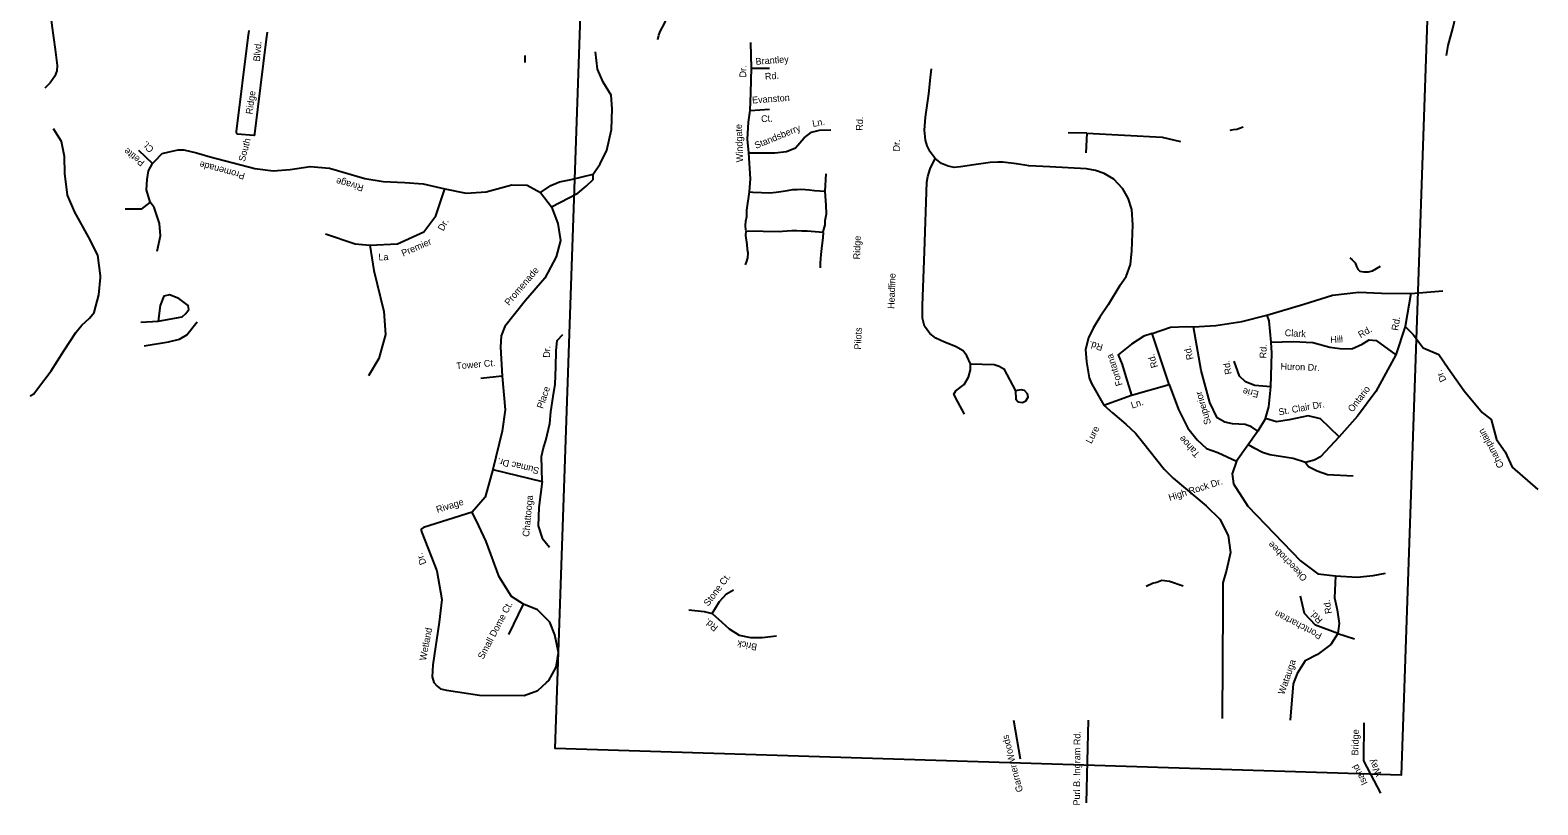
# Model space of a CAD drawing. Extents: x 2308163 to 2335412, y -96774 to 127732.
# Drawn here: x 2319297 to 2321125, y 13074 to 14013 of the extents above; entities that cross this region are included whole.
import ezdxf

# ---------------------------------------------------------------- set-up
doc = ezdxf.new("R2010")
doc.units = 0
for name, color, linetype in [('Old_Level_10', 7, 'Continuous'), ('Old_Level_35', 7, 'Continuous'), ('Old_Level_63', 7, 'Continuous')]:
    doc.layers.add(name, color=color, linetype=linetype)

msp = doc.modelspace()

# ---------------------------------------------------------------- linework, layer by layer
at = {"layer": 'Old_Level_35'}
for p, q in [((2319561.2, 14004.4), (2319562.3, 14012.8)), ((2319584, 14010.7), (2319582.9, 14002.3)), ((2319897.2, 13974.2), (2319896.9, 13982.6)), ((2320260.6, 13818.3), (2320262.1, 13839.2))]:
    msp.add_line(p, q, dxfattribs=at)
for points in [[(2320058, 14002.1), (2320058.9, 14007.1), (2320060.6, 14011.6), (2320065.8, 14021.3), (2320072.4, 14036.5), (2320082, 14060.8), (2320090.8, 14085.8), (2320104.8, 14119.7)], [(2319319.2, 14050.1), (2319319.7, 14046), (2319323, 14019.1), (2319327.2, 13989.8), (2319329.6, 13970.4), (2319329.3, 13963.9), (2319326.9, 13957.6), (2319320.9, 13949.3), (2319314.7, 13943)], [(2321014.3, 13982.6), (2321016.1, 13994.8), (2321022, 14015.4), (2321025.4, 14030.8), (2321026.1, 14038.3)], [(2319582.9, 14002.3), (2319569, 13887.5), (2319568.9, 13886.5), (2319568.8, 13886.1), (2319568.6, 13885.8), (2319568.3, 13885.7), (2319567.9, 13885.6), (2319548.4, 13887.3), (2319547.7, 13887.7), (2319547.3, 13888.3), (2319547, 13889), (2319546.9, 13889.6), (2319546.8, 13890.5), (2319561.2, 14004.4)], [(2319929.1, 13799.2), (2319960.9, 13815.9), (2319970.9, 13824.4), (2319979.3, 13832.2), (2319979.5, 13838.6), (2319988, 13851.2), (2319995.9, 13867.9), (2320001.6, 13892.8), (2320002.4, 13917.8), (2320001.4, 13934.7), (2319991.4, 13950.4), (2319984.7, 13966), (2319982.4, 13987)], [(2320169.1, 13817.2), (2320170.3, 13833.2), (2320168.1, 13864.7), (2320166.7, 13881.3), (2320167.8, 13901.9), (2320169.9, 13915.9), (2320170.6, 13937.3), (2320171.3, 13967.2), (2320170.6, 13998.4)], [(2320171.3, 13967.2), (2320193.1, 13967.2)], [(2320394, 13857.7), (2320388, 13865.9), (2320384.6, 13873.1), (2320382.4, 13880), (2320381.1, 13891.9), (2320382.5, 13907.9), (2320386.5, 13936), (2320388.5, 13956), (2320389.1, 13962.7), (2320389.5, 13966.3)], [(2320169.9, 13915.9), (2320193.4, 13917.5)], [(2319382.1, 13715.5), (2319378.7, 13740.4), (2319367.6, 13762.7), (2319350.8, 13792.9), (2319342, 13813.4), (2319338.8, 13839.5), (2319338.3, 13860.3), (2319334.8, 13878.2), (2319325.3, 13893.9)], [(2320751.9, 13892), (2320756, 13892.8), (2320759.9, 13893.4), (2320763.3, 13894.5), (2320767.6, 13896.2)], [(2320168.1, 13864.7), (2320199.8, 13864.5), (2320213.7, 13866.3), (2320224.9, 13870.6), (2320235.4, 13882.8), (2320244, 13889.7), (2320254, 13892.1), (2320267.6, 13892.4)], [(2320578, 13888.3), (2320555.4, 13888.8)], [(2320578, 13888.3), (2320577, 13864.6)], [(2320578, 13888.3), (2320669.5, 13883.5), (2320691.7, 13878.2)], [(2319445.3, 13851.6), (2319428.7, 13867.6)], [(2319442.5, 13804.9), (2319437.7, 13819.9), (2319438.7, 13832.3), (2319440.3, 13842.9), (2319445.3, 13851.6), (2319447.8, 13854.5), (2319457, 13863.7), (2319465.4, 13865.7), (2319476.1, 13868.3), (2319483.3, 13868.1), (2319498.5, 13864.6), (2319515, 13859.9)], [(2319515, 13859.9), (2319569.3, 13845.6), (2319591.4, 13842.9), (2319612.1, 13844.6), (2319636.4, 13848.2), (2319659.9, 13845.9), (2319702.4, 13833.6), (2319724.8, 13829.9), (2319751.3, 13828.5), (2319773.5, 13827.2), (2319799.8, 13820.9), (2319825.3, 13815.6), (2319849.9, 13817.2), (2319880.8, 13826), (2319899.5, 13825.3), (2319915.4, 13816.4), (2319929.1, 13799.2), (2319936.8, 13778.8), (2319940, 13758.5), (2319934.4, 13738.5), (2319920.7, 13712.9), (2319897.6, 13685.6), (2319872.4, 13654), (2319868.1, 13642.9), (2319867.1, 13629.1), (2319869.3, 13594.1), (2319872.8, 13553.1), (2319869, 13527.2), (2319858, 13480.8), (2319848.5, 13447.2), (2319832.6, 13429), (2319773.9, 13410.4), (2319770.8, 13408.5), (2319770.8, 13407), (2319771.7, 13404.5), (2319789.8, 13358.1), (2319796, 13323.5), (2319792.6, 13296), (2319784.9, 13244.1), (2319784.4, 13229.4), (2319786.1, 13222.9), (2319790.4, 13218.3), (2319794.2, 13215.2), (2319801.5, 13213.5), (2319841.7, 13207.2), (2319895.9, 13206.8), (2319912.3, 13213.1), (2319923, 13222.6), (2319925.6, 13225), (2319934.5, 13241.4), (2319937.6, 13259), (2319932.9, 13280.4), (2319927, 13295.8), (2319911.8, 13310.6), (2319894.8, 13317.6), (2319880.3, 13327), (2319865.4, 13350.6), (2319849.6, 13393.5), (2319840.9, 13412.5), (2319832.6, 13429)], [(2320436.8, 13609.1), (2320432.6, 13618.8), (2320428.2, 13624.6), (2320418.6, 13630), (2320405.3, 13635), (2320394.8, 13640), (2320387.6, 13645.7), (2320381.4, 13654.4), (2320378.7, 13664.1), (2320378.7, 13679.5), (2320381.2, 13745.1), (2320384.1, 13828.9), (2320385.2, 13835.8), (2320387.9, 13845.3), (2320394, 13857.7)], [(2320618.1, 13703.7), (2320625.7, 13714.7), (2320630.9, 13729.3), (2320632.4, 13745.8), (2320633.8, 13777.2), (2320632.6, 13796), (2320628.3, 13809.7), (2320621.8, 13820.9), (2320610.6, 13832.9), (2320599.2, 13839.5), (2320588.4, 13843.4), (2320577.5, 13845.3), (2320533.3, 13847.8), (2320507.9, 13849), (2320492.9, 13851.1), (2320476.3, 13853.5), (2320470.3, 13853.4), (2320460.8, 13852.8), (2320440.9, 13850.2), (2320424.8, 13847.5), (2320417, 13846.8), (2320409.9, 13848.4), (2320401.9, 13851.6), (2320394, 13857.7)], [(2319654.9, 13766.3), (2319691, 13754.2), (2319708.6, 13752.6), (2319742.2, 13754.4), (2319774.2, 13769), (2319788.7, 13788.2), (2319799.8, 13820.9)], [(2319915.4, 13816.4), (2319928.1, 13825.1), (2319938.8, 13829.5), (2319952.6, 13832.3), (2319979.5, 13838.6)], [(2320169.1, 13817.2), (2320173.2, 13817), (2320183.5, 13816.5), (2320193.7, 13816.1), (2320201.2, 13816.8), (2320206.8, 13817.6), (2320215.1, 13819.1), (2320221.6, 13820.1), (2320226.8, 13820.1), (2320230.9, 13820.5), (2320237, 13820.1), (2320241.7, 13819.8), (2320247.8, 13819), (2320260.6, 13818.3)], [(2319450.6, 13745.4), (2319454.8, 13764.2), (2319453.5, 13779.1), (2319447, 13798.2), (2319442.5, 13804.9), (2319431.6, 13796.4), (2319412, 13796.5)], [(2320164.7, 13770.8), (2320164.3, 13776.4), (2320164.5, 13781.9), (2320165.7, 13787.5), (2320165.6, 13795.2), (2320169.1, 13817.2)], [(2320258.5, 13768.8), (2320260.6, 13777.4), (2320260.7, 13782.5), (2320262.2, 13790.7), (2320261.8, 13800.8), (2320260.6, 13818.3)], [(2320164, 13728.9), (2320165.8, 13733.4), (2320166.9, 13737.3), (2320167.5, 13743.2), (2320166.5, 13747.5), (2320166.1, 13753.7), (2320164.7, 13764.3), (2320165.1, 13770)], [(2320165.5, 13770.2), (2320205.9, 13769.4), (2320208.9, 13769.7), (2320220.5, 13770.5), (2320226.4, 13770.5), (2320232.5, 13770.1), (2320238.8, 13770.1), (2320258.5, 13768.6)], [(2320255, 13725.2), (2320255.2, 13730.9), (2320255.4, 13736.6), (2320255.8, 13741.3), (2320256.8, 13748.6), (2320258.5, 13762.1), (2320258.9, 13768.2)], [(2319708.6, 13752.6), (2319713.5, 13721.9), (2319725.6, 13672.3), (2319727.6, 13644.6), (2319719.7, 13615.4), (2319707.1, 13594.2)], [(2320897, 13737.2), (2320899.6, 13735), (2320903.3, 13731.5), (2320905.1, 13726.9), (2320906.5, 13723.5), (2320909, 13721.2), (2320913.7, 13720.3), (2320919.4, 13720.3), (2320924.5, 13721.8), (2320934, 13727.1)], [(2319296.8, 13570.2), (2319301.3, 13572.6), (2319305.8, 13578.7), (2319322.1, 13600.5), (2319337.5, 13624.8), (2319352.2, 13646.9), (2319359.4, 13655.7), (2319368.8, 13664.4), (2319374.3, 13671.2), (2319380.2, 13692.5), (2319382.1, 13713.5), (2319382.1, 13715.5)], [(2319430.9, 13659.4), (2319452, 13660.6), (2319481.1, 13666), (2319485.5, 13669.8), (2319489.2, 13674.7), (2319488.5, 13679.8), (2319477, 13687.9), (2319465.8, 13692.7), (2319459, 13690.8), (2319454.5, 13679.7)], [(2320618.1, 13703.7), (2320603.8, 13680.6), (2320593.9, 13665.6), (2320585.9, 13652.1), (2320580, 13640.3), (2320576.5, 13626.4), (2320577.5, 13611.3), (2320580.9, 13592.1), (2320583.7, 13584.9), (2320598.7, 13558.7), (2320609.1, 13549.4), (2320625.2, 13535.8), (2320636.9, 13524.8), (2320645.5, 13514.5), (2320671.6, 13481.4), (2320682.6, 13470.3), (2320722.8, 13436.9), (2320739.2, 13420.7), (2320749.2, 13400.9), (2320752.3, 13380.1), (2320747.2, 13358.9), (2320742.8, 13343.4), (2320743.1, 13315.1), (2320742.1, 13179.2)], [(2320657.1, 13645.7), (2320679.4, 13653.2), (2320699.4, 13654.3), (2320707.3, 13653.7), (2320734.6, 13655.4), (2320766, 13660.4), (2320796.1, 13667.8), (2320841.3, 13681.1), (2320876, 13692.3), (2320907.9, 13695.7), (2320935.2, 13694.7), (2320970.9, 13694.3)], [(2320970.9, 13694.3), (2320964.1, 13654.3), (2320952.7, 13619.7), (2320928.4, 13575.2), (2320906.4, 13545.6), (2320883.8, 13520.4), (2320861.3, 13496), (2320853.8, 13492), (2320843.1, 13489.3), (2320828.2, 13494.1), (2320800, 13498.5), (2320791, 13501.3), (2320781.9, 13506.2), (2320773.9, 13510.8)], [(2320970.9, 13694.3), (2321009.6, 13697.2)], [(2319454.5, 13679.7), (2319452, 13660.6)], [(2319435, 13630.7), (2319464.7, 13635.7), (2319478, 13638.8), (2319486.8, 13644.1), (2319499.4, 13659.8)], [(2320801.6, 13635), (2320799, 13660.9), (2320796.8, 13668)], [(2319917.8, 13466.3), (2319916.9, 13496.6), (2319919.2, 13507.3), (2319922.2, 13515.9), (2319927, 13536.6), (2319928.1, 13550.7), (2319930.8, 13569.4), (2319933.3, 13584.2), (2319934.1, 13605), (2319934.7, 13624.5), (2319935.8, 13637.2), (2319942.8, 13644.4)], [(2320678, 13583.9), (2320657.1, 13645.7), (2320647.1, 13642.4), (2320632, 13632.9), (2320616.1, 13619.9), (2320620.8, 13608.2), (2320625.3, 13593), (2320632, 13570.8)], [(2320785.5, 13527.2), (2320777.5, 13532.7), (2320770.1, 13535.2), (2320754.5, 13536.2), (2320745.3, 13538.1), (2320736.2, 13543.6), (2320727, 13562.2), (2320716.5, 13601), (2320707.3, 13653.7)], [(2320801.6, 13635), (2320828.1, 13635.9), (2320852.2, 13634.6), (2320872.7, 13629), (2320884.8, 13627.5), (2320899.2, 13627.2), (2320911.9, 13632.8), (2320920.2, 13637.9), (2320928.9, 13637.3), (2320952.7, 13619.7)], [(2320964.1, 13654.3), (2320973.6, 13644.4), (2320985.9, 13628.4), (2321004.9, 13620.4), (2321016.2, 13603.5), (2321035.5, 13576.3), (2321057.5, 13549.9), (2321068.2, 13541.3), (2321074.7, 13517.2), (2321085.2, 13502.2), (2321093.7, 13483.6), (2321124.9, 13456.8)], [(2320883.8, 13520.4), (2320861.2, 13542.3), (2320846.2, 13545.8), (2320823.2, 13541.1), (2320807.8, 13538.7), (2320794.8, 13542.6), (2320798.9, 13556.6), (2320801, 13580.9), (2320802.5, 13622), (2320801.6, 13635)], [(2320429.6, 13548.1), (2320421.6, 13562.9), (2320416.9, 13572.1), (2320419, 13576), (2320429.4, 13583.7), (2320434.7, 13592.6), (2320437, 13601.5), (2320436.8, 13609.1)], [(2320436.8, 13609.1), (2320451.2, 13608.7), (2320465.6, 13608.3), (2320471.9, 13606.2), (2320477.3, 13602.8), (2320491.4, 13576.1), (2320491.9, 13566.1), (2320494.7, 13563), (2320499.9, 13562), (2320504.2, 13564.1), (2320507, 13568.4), (2320506.1, 13572.4), (2320502.3, 13576.6), (2320498.4, 13577.4), (2320493.4, 13576.7), (2320491.4, 13576.1)], [(2320801, 13580.9), (2320781.8, 13582.6), (2320770.5, 13587.2), (2320763.3, 13594.1), (2320756.8, 13612)], [(2319843.4, 13591.7), (2319869.3, 13594.5)], [(2320632, 13570.8), (2320678, 13583.9)], [(2320678, 13583.9), (2320689.1, 13553.4), (2320700.3, 13531), (2320711.7, 13516.9), (2320723.3, 13506.4), (2320736.9, 13501.4), (2320759.7, 13490.8)], [(2320598.7, 13558.7), (2320632, 13570.8)], [(2320794.8, 13542.6), (2320785.5, 13527.2), (2320759.7, 13490.8), (2320754.3, 13475.5), (2320755.7, 13463.5), (2320773.1, 13436.3), (2320836.9, 13370), (2320858.3, 13354.6), (2320879.4, 13352), (2320905.9, 13350.2), (2320925.2, 13352.3), (2320940, 13355.4)], [(2319858, 13480.8), (2319917.8, 13466.3), (2319913.4, 13434.8), (2319912.6, 13412.7), (2319917.5, 13397.7), (2319926.5, 13386.6)], [(2320843.1, 13489.3), (2320846.8, 13484.6), (2320857.2, 13479.2), (2320870, 13474.7), (2320901, 13473.2)], [(2320649.8, 13339.4), (2320657.7, 13342.9), (2320662.9, 13344.5), (2320669, 13346.6), (2320678.3, 13345.4), (2320694.8, 13339.7)], [(2320879.4, 13352), (2320878.4, 13325.5), (2320881.6, 13310.7), (2320883.8, 13294.1), (2320882.5, 13282.3), (2320873.7, 13268.8), (2320857.7, 13256.5), (2320842.8, 13248.8), (2320833.1, 13233.6), (2320828.1, 13220.9), (2320824.7, 13177)], [(2320123.7, 13306.4), (2320132.6, 13320.9), (2320141.3, 13330.3), (2320149.8, 13335.1)], [(2320882.5, 13282.3), (2320855.3, 13292), (2320842, 13306.2), (2320837.2, 13327.4)], [(2319877.1, 13280.7), (2319894.8, 13317.6)], [(2320095.5, 13310.6), (2320114.1, 13308.7), (2320123.7, 13306.4), (2320135.6, 13295.7), (2320144.3, 13287.7), (2320156.3, 13280.2), (2320170.3, 13277.1), (2320184.5, 13277.3), (2320201.8, 13279.4)], [(2320882.5, 13282.3), (2320902.4, 13275.7)], [(2320497.7, 13129.8), (2320489.4, 13176.7)], [(2320577.5, 13076.7), (2320580, 13177.2)], [(2320934.5, 13088.6), (2320913.8, 13127.8), (2320914.4, 13174)]]:
    msp.add_lwpolyline(points, dxfattribs=at)
at = {"layer": 'Old_Level_63'}
msp.add_lwpolyline([(2321015.8, 14753.3), (2320959.2, 13110.3), (2319933.5, 13142.7), (2319999.6, 15059.8)], dxfattribs=at)

# ---------------------------------------------------------------- texts
at = {"layer": 'Old_Level_10'}
for s, height, rotation, p in [('Blvd.', 8.2, 85.2272, (2319575.4, 13975.1)), ('Dr.', 8.2, 89.4385, (2320165, 13955.9)), ('Brantley', 8.2, 4.3646, (2320176.7, 13971.2)), ('Rd.', 8.2, 4.3646, (2320188, 13953.1)), ('Ridge', 8.2, 81.8623, (2319566.2, 13910.9)), ('Evanston', 8.2, 3.9715, (2320172.4, 13924.4)), ('Windgate', 8.2, 92.2238, (2320161.4, 13853.4)), ('Standsberry', 8.202, 22.4236, (2320177.1, 13869.3)), ('Ct.', 8.2, 3.9715, (2320183.3, 13901.6)), ('Ln.', 8.2, 10.8306, (2320246, 13895.9)), ('Rd.', 8.2, 87.9298, (2320306.2, 13891.3)), ('Ct.', 8.2, 134.3578, (2319447.4, 13869.6)), ('South ', 8.2, 75.4775, (2319557.1, 13853.4)), ('Dr.', 8.2, 87.0673, (2320351, 13866.1)), ('Petite', 8.2, 141.9823, (2319436.4, 13854)), ('Promenade', 8.2, 164.8185, (2319557.9, 13839.9)), ('Rivage ', 8.2, 164.9249, (2319701.8, 13825.5)), ('Dr.', 8.2, 61.5716, (2319797.7, 13769.2)), ('Premier ', 8.2, 23.573, (2319749.1, 13738.8)), ('Ridge', 8.2, 88.0247, (2320303, 13735.4)), ('La ', 8.2, 2.8628, (2319719.3, 13734.1)), ('Promenade', 8.2, 49.5056, (2319877.4, 13678.9)), ('Headline', 8.2, 88.0247, (2320344.7, 13675.4)), ('Rd.', 8.2, 80.9562, (2320955.4, 13648.7)), ('Pilots', 8.2, 87.8633, (2320304.2, 13626.1)), ('Clark', 8.2, 356.6269, (2320817.8, 13642.6)), ('Hill', 8.2, 3.1309, (2320873.5, 13634.1)), ('Rd.', 8.2, 29.8603, (2320909.9, 13639.9)), ('Dr.', 8.2, 87.4369, (2319926.9, 13616.1)), ('Rd.', 8.2, 164.5659, (2320598.2, 13632.3)), ('Fontana', 8.2, 107.7984, (2320621.5, 13583.5)), ('Rd.', 8.2, 106.6838, (2320664.3, 13605.3)), ('Rd.', 8.2, 103.6352, (2320707.4, 13614.8)), ('Rd.', 8.2, 87.8778, (2320795.6, 13615.4)), ('Tower Ct.', 8.2, 4.9538, (2319813.8, 13602.2)), ('Rd.', 8.2, 101.3226, (2320753.9, 13596.9)), ('Huron Dr.', 8.2, 358.0247, (2320812.8, 13601.9)), ('Dr.', 8.2, 116.2723, (2321014.3, 13589.3)), ('Place', 8.2, 71.0915, (2319918.5, 13554)), ('Superior', 8.2, 106.4077, (2320728.8, 13536.6)), ('Erie', 8.2, 167.3506, (2320787.1, 13575.6)), ('Ontario', 8.2, 52.5914, (2320900.2, 13549.7)), ('Ln.', 8.2, 18.5093, (2320633, 13554.6)), ('St. Clair Dr.', 8.202, 10.3937, (2320811.1, 13546.3)), ('Lure', 8.2, 62.5274, (2320583.5, 13511.4)), ('Champlain', 8.2, 118.4032, (2321084.1, 13485.2)), ('Tahoe', 8.2, 132.3947, (2320715.8, 13499.8)), ('Sumac Dr.', 8.2, 166.5432, (2319914.6, 13482.9)), ('High Rock Dr.', 8.202, 17.5209, (2320678.5, 13442.7)), ('Rivage ', 8.2, 17.4763, (2319790.6, 13428.1)), ('Chattooga', 8.2, 84.5243, (2319901.8, 13399)), ('Okeechobee', 8.2, 134.2898, (2320845.9, 13350.1)), ('Dr.', 8.2, 112.2366, (2319777.4, 13367.2)), ('Stone Ct.', 8.2, 52.9539, (2320119.1, 13314.5)), ('Small Dome Ct.', 8.202, 62.207, (2319846.2, 13250.2)), ('Pontchartran', 8.202, 152.5317, (2320863.9, 13281.7)), ('Rd.', 8.2, 134.4566, (2320864.7, 13298.9)), ('Rd.', 8.2, 99.3895, (2320875.3, 13306.6)), ('Rd.', 8.2, 140.7679, (2320131.7, 13290.2)), ('Wetland', 8.2, 79.2672, (2319776.8, 13248.8)), ('Brick', 8.2, 169.0975, (2320178.8, 13269.3)), ('Watauga', 8.2, 70.8529, (2320817.3, 13207.4)), ('Purl B. Ingram Rd.', 8.202, 89.5734, (2320569.7, 13073.6)), ('Bridge', 8.2, 88.4171, (2320907.1, 13134.2)), ('Garner Woods', 8.202, 104.4911, (2320500.7, 13091)), ('Way', 8.2, 117.301, (2320936.2, 13111.5)), ('Isand', 8.2, 117.301, (2320918.7, 13100.7))]:
    msp.add_text(s, height=height, rotation=rotation, dxfattribs=at).set_placement(p)

doc.saveas('drawing.dxf')
